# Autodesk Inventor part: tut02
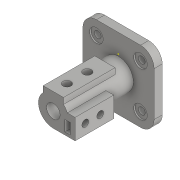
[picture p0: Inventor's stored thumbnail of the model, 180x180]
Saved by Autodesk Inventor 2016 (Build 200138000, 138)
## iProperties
Created: 2015-03
Part Number: tut02
Material: Generic
Document SubType Name: Modeling
Designer: Sandeep
Density: 1 g/cm^3
Appearance: Default
Author: Sandeep
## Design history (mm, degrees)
sketch "Sketch1"
  geometry: L1 (-32.5, -52.5)-(32.5, -52.5); L2 (52.5, -32.5)-(52.5, 32.5); L3 (32.5, 52.5)-(-32.5, 52.5); L4 (-52.5, 32.5)-(-52.5, -32.5); L5 (-52.5, -52.5)-(52.5, 52.5); L6 (52.5, -52.5)-(-52.5, 52.5); A1 r 20 centre (32.5, 32.5) between (52.5, 32.5) and (32.5, 52.5); A2 r 20 centre (32.5, -32.5) between (32.5, -52.5) and (52.5, -32.5); A3 r 20 centre (-32.5, -32.5) between (-52.5, -32.5) and (-32.5, -52.5); A4 r 20 centre (-32.5, 32.5) between (-32.5, 52.5) and (-52.5, 32.5); 1 further point
  constraints: 12 end point, 8 point on circle, 8 point on line, 8 tangent, 4 centre point, 2 equal radius, 2 midpoint, 2 parallel, 1 horizontal, 1 perpendicular
  dimensions: "d0" = 105 distance of L6.start L5.end; "d1" = 105 distance of L5.start L6.start; "d2" = 20 radius of A1; "d3" = 20 radius of A2
extrude "Extrusion1" new body sketch "Sketch1" distance "d4" = 12; taper "d5" = 0 deg
hole "Hole1" diameter "d8" = 10; stored, may be unused: countersink angle "d12" = 90 deg, drill point angle "d14" = 118 deg; dims "d9" = 6, "d10" = 20, "d11" = 2, "d13" = 8, "d15" = 10, "d16" = 10
hole "Hole2" diameter "d19" = 10; stored, may be unused: countersink angle "d23" = 90 deg, drill point angle "d25" = 118 deg; dims "d17" = 10, "d18" = 10, "d20" = 6, "d21" = 20, "d22" = 2, "d24" = 8
hole "Hole3" diameter "d28" = 10; stored, may be unused: countersink angle "d32" = 90 deg, drill point angle "d34" = 118 deg; dims "d26" = 10, "d27" = 10, "d29" = 6, "d30" = 20, "d31" = 2, "d33" = 8
hole "Hole4" diameter "d37" = 10; stored, may be unused: countersink angle "d41" = 90 deg, drill point angle "d43" = 118 deg; dims "d35" = 10, "d36" = 10, "d38" = 6, "d39" = 20, "d40" = 2, "d42" = 8
sketch "Sketch2"
  geometry: C1 r 22 at (0, 0); 1 further point
  constraints: 1 centre point, 1 coincident
  dimensions: "d44" = 44 diameter of C1
extrude "Extrusion2" join sketch "Sketch2" distance "d45" = 96; taper "d46" = 0 deg
sketch "Sketch3"
  geometry: L1 (-15, 16.093)-(-15, 25); L2 (15, 16.093)-(15, 25); L3 (-15, 25)-(15, 25); L4 (0, 0)-(20.619, 0); L5 (0, 6.043)-(0, 0); A1 r 22 centre (0, 0) between (15, 16.093) and (-15, 16.093); 1 further point
  constraints: 10 end point, 3 vertical, 2 horizontal, 2 point on circle, 1 centre point, 4 other
  dimensions: "d48" = 25 distance from line of point (0, 0) L3; "d49" = 30 distance of L1.end L2.end
extrude "Extrusion3" join sketch "Sketch3" distance "d51" = 76; taper "d52" = 0 deg
sketch "Sketch4"
  geometry: L1 (20.494, 8)-(32, 8); L2 (32, 8)-(32, -22); L3 (0, 0)-(37.067, 0); L4 (0, -22)-(32, -22); A1 r 22 centre (0, 0) between (20.494, 8) and (0, -22) reference; A2 r 22 centre (0, 0) between (0, -22) and (20.494, 8); 1 further point
  constraints: 8 end point, 5 point on circle, 2 horizontal, 2 perpendicular, 1 centre point, 1 concentric, 1 tangent
  dimensions: "d53" = 30 distance of L2.end L1.end; "d54" = 32 distance from line of L2 point (0, 0)
extrude "Extrusion4" join sketch "Sketch4" distance "d55" = 57; taper "d56" = 0 deg
sketch "Sketch5"
  geometry: L1 (17, -2)-(25, -2); L2 (25, -2)-(25, -18); L3 (25, -18)-(17, -18); L4 (17, -18)-(17, -2); 1 further point
  constraints: 8 end point, 2 parallel, 1 horizontal, 1 perpendicular
  dimensions: "d57" = 16 distance of L1.end L2.end; "d58" = 2 distance from line of point (0, 0) L1; "d59" = 25 distance from line of point (0, 0) L2; "d60" = 8 distance of L2.end L3.end
extrude "Extrusion5" cut sketch "Sketch5" distance "d61" = 50; taper "d62" = 0 deg
sketch "Sketch6"
  geometry: 1 further point
sketch "Sketch8"
  geometry: 1 further point
hole "Hole6" diameter "d77" = 20; stored, may be unused: countersink angle "d81" = 90 deg, drill point angle "d83" = 118 deg; dims "d75" = 10, "d76" = 10, "d78" = 6, "d79" = 4, "d80" = 2, "d82" = 96
hole "Hole7" diameter "d86" = 12; stored, may be unused: countersink angle "d90" = 90 deg, drill point angle "d92" = 118 deg; dims "d84" = 20, "d85" = 15, "d87" = 6, "d88" = 4, "d89" = 2, "d91" = 96
hole "Hole8" diameter "d95" = 12; stored, may be unused: countersink angle "d99" = 90 deg, drill point angle "d101" = 118 deg; dims "d93" = 50, "d94" = 15, "d96" = 6, "d97" = 4, "d98" = 2, "d100" = 96
hole "Hole10" diameter "d113" = 10; stored, may be unused: countersink angle "d117" = 90 deg, drill point angle "d119" = 118 deg; dims "d111" = 15, "d112" = 15, "d114" = 6, "d115" = 4, "d116" = 2, "d118" = 96
hole "Hole11" diameter "d122" = 10; stored, may be unused: countersink angle "d126" = 90 deg, drill point angle "d128" = 118 deg; dims "d120" = 37, "d121" = 15, "d123" = 6, "d124" = 4, "d125" = 2, "d127" = 96
body "Solid1"
